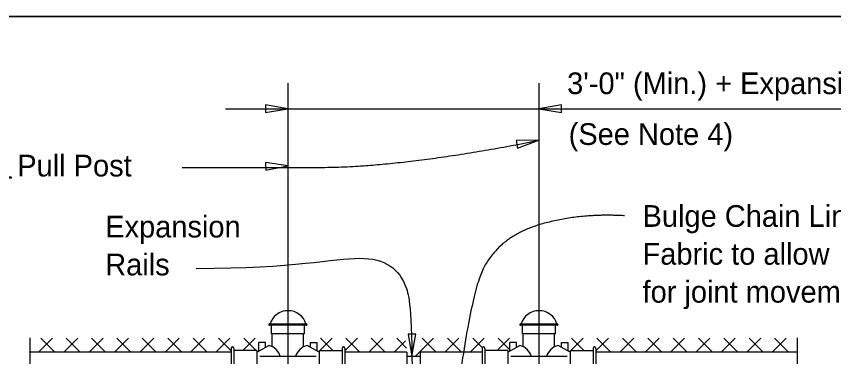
# Model space of a CAD drawing. Extents: x 0 to 41.1, y 0 to 25.9.
# Drawn here: x 23.59 to 31.18, y 22.79 to 25.95 of the extents above; entities that cross this region are included whole.
import ezdxf

# ---------------------------------------------------------------- set-up
doc = ezdxf.new("R2010")
doc.units = 0
for name, color, linetype in [('ActivePts-ConstElements', 7, 'Continuous'), ('CL_Major', 7, 'Continuous'), ('Dimension', 7, 'Continuous'), ('Miscellaneous', 7, 'Continuous'), ('Miscellaneous1', 7, 'Continuous'), ('SteelMisc', 7, 'Continuous'), ('TextStructures', 7, 'Continuous')]:
    doc.layers.add(name, color=color, linetype=linetype)

msp = doc.modelspace()

# ---------------------------------------------------------------- linework, layer by layer
at = {"layer": 'ActivePts-ConstElements'}
msp.add_lwpolyline([(0, 0), (41.0506, 0), (41.0506, 25.9461), (0, 25.9461)], close=True, dxfattribs=at)
at = {"layer": 'CL_Major'}
for p, q in [((26.1118, 25.3255), (26.1118, 12.6331)), ((28.4451, 25.3255), (28.4451, 13.7657))]:
    msp.add_line(p, q, dxfattribs=at)
at = {"layer": 'Dimension'}
msp.add_line((25.5298, 25.0883), (34.4327, 25.0883), dxfattribs=at)
for points in [[(26.1118, 25.0883), (25.9036, 25.1236), (25.9036, 25.053)], [(28.4452, 25.0883), (28.6534, 25.053), (28.6534, 25.1236)], [(28.4452, 24.7949), (28.234, 24.7914), (28.2469, 24.722)], [(26.1118, 24.5582), (25.9026, 24.5871), (25.9047, 24.5166)], [(27.2647, 22.7854), (27.3, 22.9937), (27.2295, 22.9937)]]:
    msp.add_lwpolyline(points, close=True, dxfattribs=at)
for points in [[(23.712, 22.9593), (23.712, 21.0031), (23.8154, 21.0031), (23.712, 20.9581), (23.6087, 20.9131), (23.712, 20.9131), (23.712, 20.0194)], [(30.8451, 22.9593), (30.8451, 21.0031), (30.9484, 21.0031), (30.8451, 20.9581), (30.7418, 20.9131), (30.8451, 20.9131), (30.8451, 20.0194)]]:
    msp.add_lwpolyline(points, dxfattribs=at)
for points, degree in [([(25.1277, 24.5426), (25.5814, 24.5426), (27.1777, 24.5426), (28.4451, 24.7949)], 2), ([(29.2401, 24.0936), (28.8116, 24.1189), (28.0806, 23.9002), (27.7781, 23.3115), (27.6101, 21.8045)], 2), ([(25.2573, 23.6051), (26.1819, 23.6051), (26.8868, 23.7931), (27.2773, 23.5118), (27.2785, 22.9517), (27.2785, 17.3687)], 3)]:
    msp.add_open_spline(points, degree=degree, dxfattribs=at)
at = {"layer": 'Miscellaneous'}
for p, q in [((23.9227, 22.9573), (23.7925, 22.8271)), ((23.9454, 22.8271), (23.8152, 22.9573)), ((24.1584, 22.9573), (24.0282, 22.8271)), ((24.1811, 22.8271), (24.0509, 22.9573)), ((24.3941, 22.9573), (24.2639, 22.8271)), ((24.4168, 22.8271), (24.2866, 22.9573)), ((24.6298, 22.9573), (24.4996, 22.8271)), ((24.6525, 22.8271), (24.5223, 22.9573)), ((24.8655, 22.9573), (24.7353, 22.8271)), ((24.8882, 22.8271), (24.758, 22.9573)), ((25.1012, 22.9573), (24.971, 22.8271)), ((25.1239, 22.8271), (24.9937, 22.9573)), ((25.3369, 22.9573), (25.2067, 22.8271)), ((25.3596, 22.8271), (25.2294, 22.9573)), ((25.5726, 22.9573), (25.4424, 22.8271)), ((25.5825, 22.8399), (25.4651, 22.9573)), ((25.8083, 22.9573), (25.6935, 22.8425)), ((25.8156, 22.8425), (25.7008, 22.9573)), ((26.4081, 22.8425), (26.5228, 22.9573)), ((26.4154, 22.9573), (26.5301, 22.8425)), ((26.6412, 22.8399), (26.7585, 22.9573)), ((26.6511, 22.9573), (26.7812, 22.8271)), ((26.864, 22.8271), (26.9942, 22.9573)), ((26.8868, 22.9573), (27.0169, 22.8271)), ((27.1225, 22.9573), (27.2146, 22.8651)), ((27.2938, 22.7854), (27.4656, 22.9573)), ((27.3582, 22.9573), (27.4883, 22.8271)), ((27.5712, 22.8271), (27.7013, 22.9573)), ((27.5939, 22.9573), (27.724, 22.8271)), ((27.8069, 22.8271), (27.937, 22.9573)), ((27.8296, 22.9573), (27.9158, 22.8711)), ((28.058, 22.8425), (28.1727, 22.9573)), ((28.0653, 22.9573), (28.1743, 22.8483)), ((28.7414, 22.8425), (28.8561, 22.9573)), ((28.7487, 22.9573), (28.8634, 22.8425)), ((28.9745, 22.8399), (29.0918, 22.9573)), ((28.9844, 22.9573), (29.1146, 22.8271)), ((29.1974, 22.8271), (29.3275, 22.9573)), ((29.2201, 22.9573), (29.3503, 22.8271)), ((29.4331, 22.8271), (29.5632, 22.9573)), ((29.4558, 22.9573), (29.586, 22.8271)), ((29.6688, 22.8271), (29.7989, 22.9573)), ((29.6915, 22.9573), (29.8217, 22.8271)), ((29.9045, 22.8271), (30.0347, 22.9573)), ((29.9272, 22.9573), (30.0574, 22.8271)), ((30.1402, 22.8271), (30.2704, 22.9573)), ((30.1629, 22.9573), (30.2931, 22.8271)), ((30.3759, 22.8271), (30.5061, 22.9573)), ((30.3986, 22.9573), (30.5288, 22.8271)), ((30.6116, 22.8271), (30.7418, 22.9573)), ((30.6343, 22.9573), (30.7645, 22.8271)), ((27.0997, 22.8271), (27.2045, 22.9319))]:
    msp.add_line(p, q, dxfattribs=at)
at = {"layer": 'Miscellaneous1'}
msp.add_lwpolyline([(0, 25.9461), (41.0506, 25.9461), (41.0506, 0), (0, 0)], close=True, dxfattribs=at)
at = {"layer": 'SteelMisc'}
for p, q in [((25.9395, 23.0892), (26.2841, 23.0892)), ((26.2841, 23.077), (25.9395, 23.077)), ((25.9578, 22.9972), (25.9578, 23.077)), ((26.2659, 22.9972), (26.2659, 23.077)), ((28.2729, 23.0892), (28.6174, 23.0892)), ((28.6174, 23.077), (28.2729, 23.077)), ((28.2911, 22.9972), (28.2911, 23.077)), ((28.5992, 22.9972), (28.5992, 23.077)), ((26.2659, 22.9972), (25.9578, 22.9972)), ((25.966, 22.8773), (25.966, 22.9972)), ((26.2577, 22.8773), (26.2577, 22.9972)), ((28.5992, 22.9972), (28.2911, 22.9972)), ((28.2994, 22.8773), (28.2994, 22.9972)), ((28.591, 22.8773), (28.591, 22.9972)), ((25.8222, 22.8278), (25.9331, 22.8892)), ((25.8409, 22.8381), (25.8409, 22.9156)), ((25.9034, 22.9156), (25.8409, 22.9156)), ((25.9034, 22.8727), (25.9034, 22.9156)), ((26.4014, 22.8278), (26.2905, 22.8892)), ((26.3202, 22.8739), (26.3202, 22.9156)), ((26.3202, 22.9156), (26.3827, 22.9156)), ((26.3827, 22.8381), (26.3827, 22.9156)), ((28.1556, 22.8278), (28.2664, 22.8892)), ((28.1743, 22.8381), (28.1743, 22.9156)), ((28.2368, 22.9156), (28.1743, 22.9156)), ((28.2368, 22.8727), (28.2368, 22.9156)), ((28.7347, 22.8278), (28.6239, 22.8892)), ((28.6535, 22.8739), (28.6535, 22.9156)), ((28.6535, 22.9156), (28.716, 22.9156)), ((28.716, 22.8381), (28.716, 22.9156)), ((25.5825, 22.8271), (23.712, 22.8271)), ((25.5824, 22.8621), (25.5824, 22.5524)), ((25.6093, 22.8621), (25.6093, 22.5524)), ((25.8222, 22.8425), (25.6093, 22.8425)), ((25.8222, 22.8425), (25.8222, 22.5703)), ((26.4014, 22.8425), (26.4014, 22.5703)), ((26.4014, 22.8425), (26.6143, 22.8425)), ((26.6143, 22.8621), (26.6143, 22.5524)), ((26.6411, 22.8621), (26.6411, 22.5524)), ((27.216, 22.8271), (26.6412, 22.8271)), ((27.216, 22.8271), (27.216, 22.5875)), ((27.341, 22.8271), (27.341, 22.5875)), ((27.9158, 22.8271), (27.341, 22.8271)), ((27.9158, 22.8621), (27.9158, 22.5524)), ((27.9426, 22.8621), (27.9426, 22.5524)), ((28.1556, 22.8425), (27.9426, 22.8425)), ((28.1556, 22.8425), (28.1556, 22.5703)), ((28.7347, 22.8425), (28.7347, 22.5703)), ((28.7347, 22.8425), (28.9477, 22.8425)), ((28.9477, 22.8621), (28.9477, 22.5524)), ((28.9745, 22.8621), (28.9745, 22.5524)), ((30.845, 22.8271), (28.9745, 22.8271)), ((26.3742, 22.7852), (25.8494, 22.7852)), ((27.341, 22.7854), (27.216, 22.7854)), ((28.7075, 22.7852), (28.1827, 22.7852))]:
    msp.add_line(p, q, dxfattribs=at)
for centre, radius, start, end in [((25.9397, 23.0829), 0.00613, 91.1647, 268.8353), ((26.284, 23.0829), 0.00613, 271.1647, 88.8353), ((28.273, 23.0829), 0.00613, 91.1647, 268.8353), ((28.6173, 23.0829), 0.00613, 271.1647, 88.8353), ((25.596, 22.862), 0.0134, 0, 180), ((26.6277, 22.862), 0.0134, 0, 180), ((27.9293, 22.862), 0.0134, 0, 180), ((28.961, 22.862), 0.0134, 0, 180)]:
    msp.add_arc(centre, radius, start, end, dxfattribs=at)
for centre, major_axis, start_param, end_param in [((26.1125, 23.0482), (0.1711, 0), 0.252602, 2.888574), ((28.4458, 23.0482), (0.1711, 0), 0.252602, 2.888574), ((25.8986, 22.7532), (0.146, 0), 0.231126, 1.331255), ((26.325, 22.7532), (-0.146, 0), 4.95193, 6.05206), ((28.2319, 22.7532), (0.146, 0), 0.231126, 1.331255), ((28.6584, 22.7532), (-0.146, 0), 4.95193, 6.05206)]:
    msp.add_ellipse(centre, major_axis=major_axis, ratio=0.957868, start_param=start_param, end_param=end_param, dxfattribs=at)

# ---------------------------------------------------------------- texts
at = {"layer": 'Dimension'}
for s, p in [('Bulge Chain Link ', (29.4081, 23.9909)), ('Expansion', (24.4131, 23.8921)), ('Fabric to allow ', (29.4081, 23.6389)), ('Rails', (24.4131, 23.5401)), ('for joint movement', (29.4081, 23.2869))]:
    msp.add_text(s, height=0.2016, dxfattribs=at).set_placement(p)
at = {"layer": 'TextStructures'}
for s, p in [('3\'-0" (Min.) + Expansion Joint Opening', (28.7069, 25.2234)), ('(See Note 4)', (28.7212, 24.7517)), ('℄ Pull Post', (23.4113, 24.4589))]:
    msp.add_text(s, height=0.2016, dxfattribs=at).set_placement(p)

doc.saveas('drawing.dxf')
